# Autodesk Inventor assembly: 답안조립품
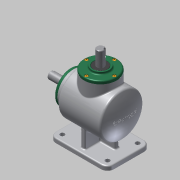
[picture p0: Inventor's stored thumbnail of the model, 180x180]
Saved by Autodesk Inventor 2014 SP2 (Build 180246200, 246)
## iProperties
Created: 2016-09
Part Number: 답안조립품
Document SubType Name: Assembly
Designer: 1sil_ho3333
Author: 1sil_ho3333
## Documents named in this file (14)
- C:\Users\1sil_ho3333\Desktop\460908V1015\답안조립품.iam
- C:\Users\1sil_ho3333\Desktop\460908V1015\본체.ipt
- C:\Users\1sil_ho3333\Desktop\460908V1015\M4.ipt
- C:\Users\1sil_ho3333\Desktop\460908V1015\메인 베벨기어.ipt
- C:\Users\1sil_ho3333\Desktop\460908V1015\메인 축.ipt
- 메인 축.ipt
- C:\Users\1sil_ho3333\Desktop\460908V1015\베어링 6203.ipt
- C:\Users\1sil_ho3333\Desktop\460908V1015\서브 베벨기어.ipt
- C:\Users\1sil_ho3333\Desktop\460908V1015\서브 축.ipt
- 서브 축.ipt
- C:\Users\1sil_ho3333\Desktop\460908V1015\오일실 17 32 8.ipt
- C:\Users\1sil_ho3333\Desktop\460908V1015\커버.ipt
- C:\Users\1sil_ho3333\Desktop\460908V1015\키 4x4.ipt
- C:\Users\1sil_ho3333\Desktop\460908V1015\키 5x5.ipt
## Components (8 placed, 1 different names)
1. M4:2
2. M4:3
3. M4:4
4. M4:5
5. M4:1
6. M4:6
7. M4:7
8. M4:8
